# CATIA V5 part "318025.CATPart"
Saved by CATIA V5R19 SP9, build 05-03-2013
Part number: 318025
Source: Unknown
Bounding box of the stored display mesh (mm): x -86 to 342.005, y -364 to 364, z 381.245 to 440
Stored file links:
  D:\16-SIL\kale oto\R19_V2\318025.CATPart
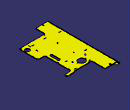
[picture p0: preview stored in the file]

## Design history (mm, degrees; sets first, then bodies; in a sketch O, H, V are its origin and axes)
Set1
  Line1 "Project.1": stored without definition
Body1 "120\\5\\MANIFOLD_SOLID_BREP #16656" (main body)
  Solid1: solid without history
